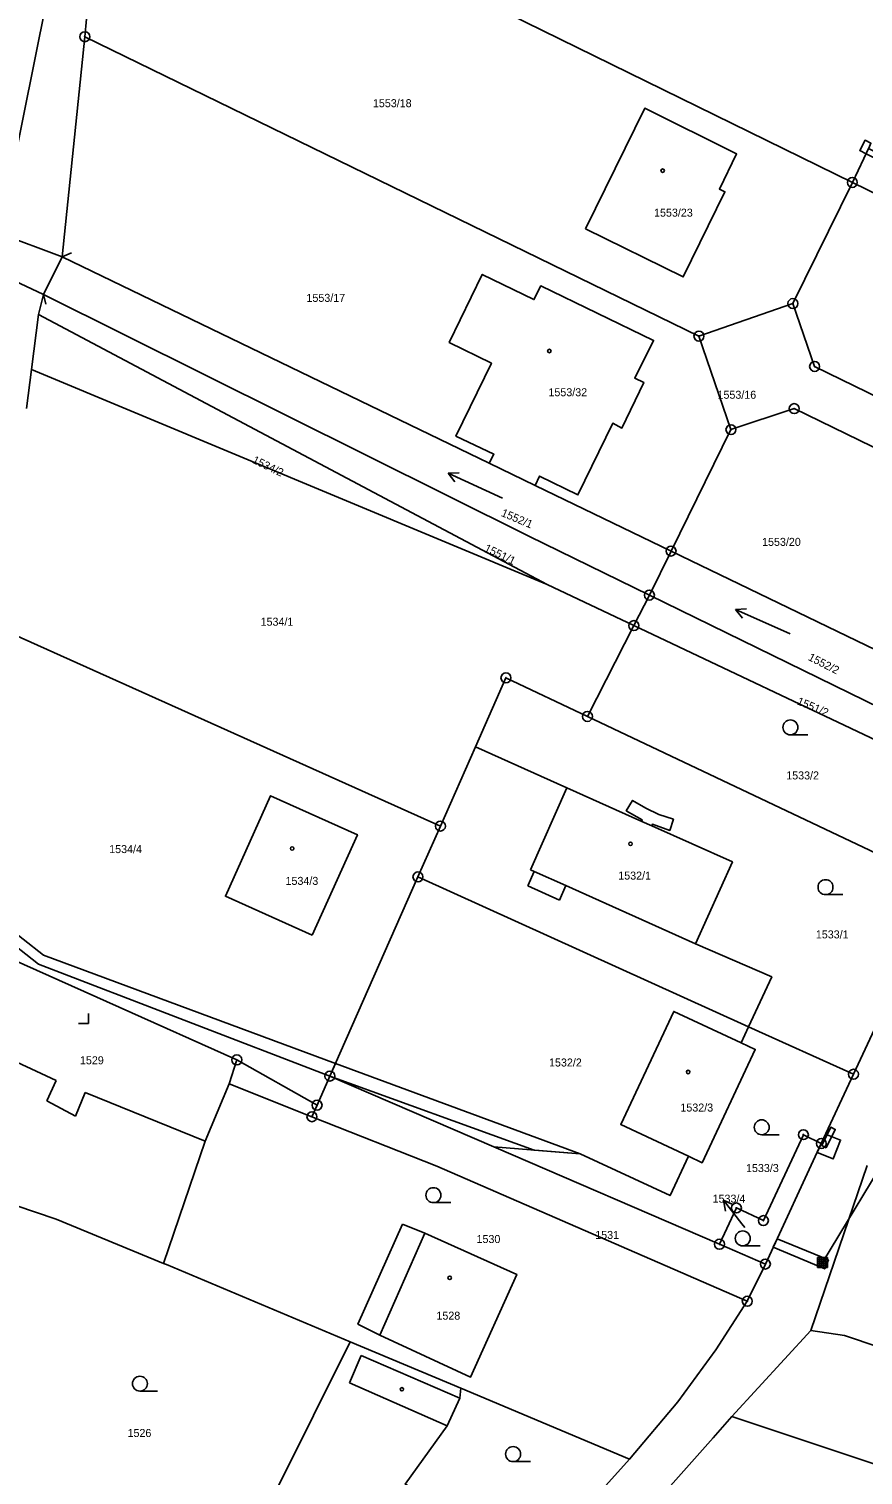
# Model space of a CAD drawing. Extents: x -587171 to -555306, y -1167727 to -1074732.
# Drawn here: x -559814.4 to -559730.7, y -1075878.4 to -1075733.4 of the extents above; entities that cross this region are included whole.
import ezdxf

# ---------------------------------------------------------------- set-up
doc = ezdxf.new("R2010")
doc.units = 0
for name, color, linetype in [('Hranice parcel', 7, 'Continuous'), ('Parcelní čísla', 7, 'Continuous'), ('Pop  PČ popisy', 7, 'Continuous'), ('Poz předměty', 7, 'Continuous'), ('Vnitřní kresba', 7, 'Continuous'), ('Věcná břemena k části', 7, 'Continuous'), ('Značky bodu BP', 7, 'Continuous'), ('Značky budov', 7, 'Continuous'), ('Značky kultur', 7, 'Continuous')]:
    doc.layers.add(name, color=color, linetype=linetype)

msp = doc.modelspace()

# ---------------------------------------------------------------- linework, layer by layer
at = {"layer": 'Hranice parcel'}
for p, q in [((-559731.8, -1075748.76), (-559796.1, -1075717.18)), ((-559811.02, -1075756.21), (-559808.75, -1075734.14)), ((-559747.18, -1075764.18), (-559808.75, -1075734.14)), ((-559730.08, -1075745.15), (-559731.8, -1075748.76)), ((-559737.76, -1075760.91), (-559731.8, -1075748.76)), ((-559692.3, -1075768.16), (-559731.8, -1075748.76)), ((-559812.91, -1075760), (-559811.02, -1075756.21)), ((-559811.02, -1075756.21), (-559768.2, -1075776.93)), ((-559813.39, -1075762.02), (-559812.91, -1075760)), ((-559737.76, -1075760.91), (-559747.18, -1075764.18)), ((-559814.1, -1075767.51), (-559813.39, -1075762.02)), ((-559813.39, -1075762.02), (-559762.4, -1075789.09)), ((-559747.18, -1075764.18), (-559743.97, -1075773.56)), ((-559814.61, -1075771.43), (-559814.1, -1075767.51)), ((-559762.4, -1075789.09), (-559814.1, -1075767.51)), ((-559749.98, -1075785.74), (-559743.97, -1075773.56)), ((-559763.6, -1075779.15), (-559768.2, -1075776.93)), ((-559763.6, -1075779.15), (-559749.98, -1075785.74)), ((-559752.15, -1075790.16), (-559749.98, -1075785.74)), ((-559749.98, -1075785.74), (-559714.26, -1075803.02)), ((-559762.4, -1075789.09), (-559753.71, -1075793.22)), ((-559753.71, -1075793.22), (-559752.15, -1075790.16)), ((-559717.12, -1075807.32), (-559752.15, -1075790.16)), ((-559773.1, -1075813.33), (-559815.81, -1075794.14)), ((-559753.71, -1075793.22), (-559758.36, -1075802.33)), ((-559753.71, -1075793.22), (-559718.54, -1075809.9)), ((-559722.85, -1075819.18), (-559758.36, -1075802.33)), ((-559769.59, -1075805.38), (-559773.1, -1075813.33)), ((-559775.35, -1075818.43), (-559773.1, -1075813.33)), ((-559784.18, -1075838.41), (-559775.35, -1075818.43)), ((-559775.35, -1075818.43), (-559742.2, -1075833.46)), ((-559722.85, -1075819.18), (-559731.69, -1075838.23)), ((-559742.95, -1075835.07), (-559742.2, -1075833.46)), ((-559742.2, -1075833.46), (-559731.69, -1075838.23)), ((-559785.98, -1075842.49), (-559794.29, -1075839.2)), ((-559767.73, -1075845.51), (-559784.18, -1075838.41)), ((-559731.69, -1075838.23), (-559734.91, -1075845.17)), ((-559745.12, -1075855.28), (-559767.73, -1075845.51)), ((-559734.91, -1075845.17), (-559740.52, -1075857.27)), ((-559735.95, -1075863.92), (-559730.31, -1075847.37)), ((-559740.52, -1075857.27), (-559745.12, -1075855.28)), ((-559740.52, -1075857.27), (-559742.33, -1075861)), ((-559743.87, -1075872.57), (-559735.95, -1075863.92)), ((-559771.04, -1075869.73), (-559782.14, -1075865.06)), ((-559771.04, -1075869.73), (-559754.13, -1075876.85))]:
    msp.add_line(p, q, dxfattribs=at)
for points in [[(-559808.75, -1075734.14), (-559808.57, -1075732.35), (-559796.1, -1075717.18)], [(-559812.62, -1075730.76), (-559817.32, -1075753.87), (-559818.88, -1075757.17), (-559822.15, -1075761.67)], [(-559758.56, -1075753.42), (-559752.61, -1075741.32), (-559743.41, -1075745.89), (-559745.12, -1075749.43), (-559744.58, -1075749.7), (-559748.75, -1075758.23), (-559758.56, -1075753.42)], [(-559768.2, -1075776.93), (-559767.73, -1075776.03), (-559771.54, -1075774.2), (-559767.99, -1075766.9), (-559772.22, -1075764.81), (-559768.9, -1075757.99), (-559763.72, -1075760.51), (-559763.04, -1075759.14), (-559751.73, -1075764.6), (-559753.61, -1075768.39), (-559752.72, -1075768.82), (-559754.91, -1075773.41), (-559755.83, -1075772.92), (-559759.31, -1075780.1), (-559763.15, -1075778.22), (-559763.6, -1075779.15)], [(-559752.15, -1075790.16), (-559764.23, -1075784.25), (-559812.91, -1075760)], [(-559700.23, -1075780.74), (-559705.08, -1075782.11), (-559735.58, -1075767.22), (-559737.76, -1075760.91)], [(-559743.97, -1075773.56), (-559737.63, -1075771.45), (-559707.59, -1075786.09), (-559706.7, -1075791.01)], [(-559758.36, -1075802.33), (-559766.53, -1075798.46), (-559769.59, -1075805.38)], [(-559769.59, -1075805.38), (-559760.42, -1075809.49), (-559752.91, -1075812.86), (-559752.88, -1075812.71), (-559754.47, -1075811.8), (-559753.84, -1075810.76), (-559752.51, -1075811.55), (-559751.19, -1075812.16), (-559749.74, -1075812.64), (-559750.1, -1075813.77), (-559751.85, -1075813.14), (-559751.91, -1075813.31), (-559743.83, -1075816.93), (-559747.51, -1075825.13), (-559739.88, -1075828.47), (-559742.2, -1075833.46)], [(-559785.96, -1075824.28), (-559781.43, -1075814.2), (-559790.13, -1075810.29), (-559794.65, -1075820.37), (-559785.96, -1075824.28)], [(-559794.29, -1075839.2), (-559793.51, -1075836.79), (-559817.1, -1075826.2)], [(-559748.24, -1075846.45), (-559755.02, -1075843.27), (-559749.7, -1075831.92), (-559742.95, -1075835.07)], [(-559742.95, -1075835.07), (-559741.54, -1075835.73), (-559746.86, -1075847.1), (-559748.24, -1075846.45)], [(-559800.85, -1075857.2), (-559796.69, -1075844.93), (-559794.29, -1075839.2)], [(-559784.18, -1075838.41), (-559785.47, -1075841.33), (-559785.98, -1075842.49)], [(-559742.33, -1075861), (-559773.46, -1075847.44), (-559785.98, -1075842.49)], [(-559745.12, -1075855.28), (-559743.43, -1075851.64), (-559740.72, -1075852.91), (-559736.71, -1075844.29), (-559734.91, -1075845.17)], [(-559767.73, -1075845.51), (-559759.1, -1075846.22), (-559750.07, -1075850.4), (-559748.24, -1075846.45)], [(-559821, -1075850.76), (-559817.67, -1075850.72), (-559811.62, -1075852.78), (-559800.85, -1075857.2)], [(-559776.9, -1075853.26), (-559781.38, -1075863.29), (-559779.17, -1075864.41), (-559770.08, -1075868.61), (-559765.45, -1075858.31), (-559774.66, -1075854.18), (-559776.9, -1075853.26)], [(-559800.85, -1075857.2), (-559800.57, -1075857.31), (-559782.14, -1075865.06)], [(-559742.33, -1075861), (-559745.48, -1075865.87), (-559749.31, -1075871.1), (-559754.13, -1075876.85)], [(-559735.95, -1075863.92), (-559732.58, -1075864.43), (-559707.97, -1075872.72), (-559694.43, -1075877.61)], [(-559782.14, -1075865.06), (-559793.14, -1075887.17), (-559787.95, -1075890.13), (-559783.64, -1075892.41), (-559785.07, -1075895.16), (-559777.29, -1075899.22)], [(-559777.29, -1075899.22), (-559774.71, -1075894.36), (-559773.08, -1075895.27), (-559772.14, -1075894.77), (-559771.44, -1075893.27), (-559771.43, -1075892.12), (-559773.03, -1075891.2), (-559770.46, -1075886.37), (-559773.26, -1075884.9), (-559771.75, -1075881.96), (-559776.65, -1075879.35), (-559772.43, -1075873.5), (-559771.15, -1075870.71), (-559771.04, -1075869.73)], [(-559759.39, -1075890.96), (-559756.96, -1075887.31), (-559745.77, -1075874.71), (-559743.87, -1075872.57)], [(-559718.92, -1075880.89), (-559742.59, -1075873), (-559743.87, -1075872.57)], [(-559754.13, -1075876.85), (-559760.1, -1075883.46), (-559765.88, -1075889.07), (-559774.97, -1075900.54), (-559781.59, -1075907.31)]]:
    msp.add_lwpolyline(points, dxfattribs=at)
at = {"layer": 'Pop  PČ popisy'}
for p, q in [((-559742.88, -1075853.22), (-559744.73, -1075850.85)), ((-559744.73, -1075850.85), (-559743.72, -1075851.34)), ((-559744.73, -1075850.85), (-559744.51, -1075851.95)), ((-559742.59, -1075853.59), (-559742.88, -1075853.22))]:
    msp.add_line(p, q, dxfattribs=at)
at = {"layer": 'Poz předměty'}
for p, q in [((-559713.43, -1075821.67), (-559734.8, -1075857.12)), ((-559735.3, -1075856.62), (-559734.3, -1075856.62)), ((-559735.3, -1075857.62), (-559735.3, -1075856.62)), ((-559735.1, -1075857.62), (-559735.1, -1075856.62)), ((-559734.9, -1075857.62), (-559734.9, -1075856.62)), ((-559734.7, -1075857.62), (-559734.7, -1075856.62)), ((-559734.5, -1075857.62), (-559734.5, -1075856.62)), ((-559734.3, -1075857.62), (-559734.3, -1075856.62)), ((-559735.3, -1075856.82), (-559734.3, -1075856.82)), ((-559735.3, -1075857.02), (-559734.3, -1075857.02)), ((-559735.3, -1075857.22), (-559734.3, -1075857.22)), ((-559735.3, -1075857.42), (-559734.3, -1075857.42)), ((-559735.3, -1075857.62), (-559734.3, -1075857.62))]:
    msp.add_line(p, q, dxfattribs=at)
at = {"layer": 'Vnitřní kresba'}
for p, q in [((-559817.32, -1075753.87), (-559811.02, -1075756.21)), ((-559810.1, -1075755.82), (-559811.02, -1075756.21)), ((-559818.88, -1075757.17), (-559812.91, -1075760)), ((-559812.67, -1075760.97), (-559812.91, -1075760)), ((-559760.42, -1075809.49), (-559764.08, -1075817.71)), ((-559751.91, -1075813.31), (-559752.91, -1075812.86)), ((-559764.34, -1075819.33), (-559763.7, -1075817.88)), ((-559764.08, -1075817.71), (-559763.7, -1075817.88)), ((-559763.7, -1075817.88), (-559760.52, -1075819.3)), ((-559761.17, -1075820.77), (-559764.34, -1075819.33)), ((-559760.52, -1075819.3), (-559761.17, -1075820.77)), ((-559760.52, -1075819.3), (-559747.51, -1075825.13)), ((-559821.3, -1075834.37), (-559811.62, -1075838.87)), ((-559793.51, -1075836.79), (-559785.47, -1075841.33)), ((-559811.62, -1075838.87), (-559812.56, -1075840.9)), ((-559809.69, -1075842.45), (-559808.71, -1075840.05)), ((-559808.71, -1075840.05), (-559796.69, -1075844.93)), ((-559812.56, -1075840.9), (-559809.69, -1075842.45)), ((-559774.66, -1075854.18), (-559779.17, -1075864.41)), ((-559781.04, -1075866.45), (-559782.22, -1075869.19)), ((-559771.15, -1075870.71), (-559781.04, -1075866.45)), ((-559782.22, -1075869.19), (-559772.43, -1075873.5))]:
    msp.add_line(p, q, dxfattribs=at)
at = {"layer": 'Věcná břemena k části'}
for points in [[(-559730.43, -1075745.88), (-559690.65, -1075765.53), (-559690.3, -1075764.99), (-559730.17, -1075745.34), (-559730.08, -1075745.15), (-559729.93, -1075744.83), (-559730.53, -1075744.53), (-559731.05, -1075745.57)], [(-559816.98, -1075823.08), (-559817.03, -1075824.32), (-559813.39, -1075827.17), (-559784.18, -1075838.41), (-559783.62, -1075837.14), (-559812.89, -1075826.29)], [(-559783.62, -1075837.14), (-559784.18, -1075838.41), (-559763.7, -1075845.84), (-559759.1, -1075846.22)], [(-559734.42, -1075845.6), (-559733.52, -1075843.76), (-559733.97, -1075843.54), (-559734.87, -1075845.38)], [(-559734.48, -1075844.24), (-559735.33, -1075846.09), (-559733.73, -1075846.72), (-559732.98, -1075844.83)], [(-559734.18, -1075856.84), (-559739.35, -1075854.74), (-559739.73, -1075855.58), (-559734.57, -1075857.76)]]:
    msp.add_lwpolyline(points, close=True, dxfattribs=at)
at = {"layer": 'Značky bodu BP'}
for centre, radius in [((-559808.75, -1075734.14), 0.5), ((-559808.75, -1075734.14), 0.0303), ((-559731.8, -1075748.76), 0.5), ((-559731.8, -1075748.76), 0.0303), ((-559737.76, -1075760.91), 0.5), ((-559737.76, -1075760.91), 0.0303), ((-559747.18, -1075764.18), 0.5), ((-559747.18, -1075764.18), 0.0303), ((-559735.58, -1075767.22), 0.5), ((-559735.58, -1075767.22), 0.0303), ((-559737.63, -1075771.45), 0.5), ((-559737.63, -1075771.45), 0.0303), ((-559743.97, -1075773.56), 0.5), ((-559743.97, -1075773.56), 0.0303), ((-559749.98, -1075785.74), 0.5), ((-559749.98, -1075785.74), 0.0303), ((-559752.15, -1075790.16), 0.5), ((-559752.15, -1075790.16), 0.0303), ((-559753.71, -1075793.22), 0.5), ((-559753.71, -1075793.22), 0.0303), ((-559766.53, -1075798.46), 0.5), ((-559766.53, -1075798.46), 0.0303), ((-559758.36, -1075802.33), 0.5), ((-559758.36, -1075802.33), 0.0303), ((-559773.1, -1075813.33), 0.5), ((-559773.1, -1075813.33), 0.0303), ((-559775.35, -1075818.43), 0.5), ((-559775.35, -1075818.43), 0.0303), ((-559793.51, -1075836.79), 0.5), ((-559793.51, -1075836.79), 0.0303), ((-559731.69, -1075838.23), 0.5), ((-559784.18, -1075838.41), 0.5), ((-559784.18, -1075838.41), 0.0303), ((-559731.69, -1075838.23), 0.0303), ((-559785.98, -1075842.49), 0.5), ((-559785.47, -1075841.33), 0.5), ((-559785.47, -1075841.33), 0.0303), ((-559785.98, -1075842.49), 0.0303), ((-559736.71, -1075844.29), 0.5), ((-559736.71, -1075844.29), 0.0303), ((-559734.91, -1075845.17), 0.5), ((-559734.91, -1075845.17), 0.0303), ((-559743.43, -1075851.64), 0.5), ((-559743.43, -1075851.64), 0.0303), ((-559740.72, -1075852.91), 0.5), ((-559740.72, -1075852.91), 0.0303), ((-559745.12, -1075855.28), 0.5), ((-559745.12, -1075855.28), 0.0303), ((-559740.52, -1075857.27), 0.5), ((-559740.52, -1075857.27), 0.0303), ((-559742.33, -1075861), 0.5), ((-559742.33, -1075861), 0.0303)]:
    msp.add_circle(centre, radius, dxfattribs=at)
at = {"layer": 'Značky budov'}
for centre in [(-559750.82, -1075747.57), (-559762.18, -1075765.67), (-559787.97, -1075815.58), (-559754.04, -1075815.11), (-559748.26, -1075838), (-559772.17, -1075858.65), (-559776.96, -1075869.83)]:
    msp.add_circle(centre, 0.175, dxfattribs=at)
at = {"layer": 'Značky kultur'}
for p, q in [((-559772.33, -1075777.92), (-559771.23, -1075777.88)), ((-559766.89, -1075780.45), (-559772.33, -1075777.92)), ((-559772.33, -1075777.92), (-559771.66, -1075778.78)), ((-559743.5, -1075791.61), (-559742.41, -1075791.55)), ((-559738.02, -1075794.05), (-559743.5, -1075791.61)), ((-559743.5, -1075791.61), (-559742.81, -1075792.47)), ((-559738.01, -1075804.18), (-559736.26, -1075804.18)), ((-559734.49, -1075820.21), (-559732.74, -1075820.21)), ((-559809.39, -1075833.13), (-559808.39, -1075833.13)), ((-559808.39, -1075833.13), (-559808.39, -1075832.13)), ((-559740.89, -1075844.3), (-559739.14, -1075844.3)), ((-559773.8, -1075851.11), (-559772.05, -1075851.11)), ((-559742.79, -1075855.45), (-559741.04, -1075855.45)), ((-559803.23, -1075870.02), (-559801.48, -1075870.02)), ((-559765.81, -1075877.09), (-559764.06, -1075877.09))]:
    msp.add_line(p, q, dxfattribs=at)
for centre in [(-559738.01, -1075803.43), (-559734.49, -1075819.46), (-559740.89, -1075843.55), (-559773.8, -1075850.36), (-559742.79, -1075854.7), (-559803.23, -1075869.27), (-559765.81, -1075876.34)]:
    msp.add_circle(centre, 0.75, dxfattribs=at)

# ---------------------------------------------------------------- texts
at = {"layer": 'Parcelní čísla'}
for s, p in [('1553/18', (-559779.87, -1075741.21)), ('1553/23', (-559751.68, -1075752.19)), ('1553/17', (-559786.53, -1075760.74)), ('1553/32', (-559762.27, -1075770.21)), ('1553/16', (-559745.32, -1075770.46)), ('1553/20', (-559740.85, -1075785.22)), ('1534/1', (-559791.13, -1075793.23)), ('1533/2', (-559738.43, -1075808.65)), ('1534/4', (-559806.31, -1075816.04)), ('1534/3', (-559788.63, -1075819.23)), ('1532/1', (-559755.27, -1075818.7)), ('1533/1', (-559735.46, -1075824.6)), ('1529', (-559809.24, -1075837.23)), ('1532/2', (-559762.21, -1075837.45)), ('1532/3', (-559749.04, -1075841.97)), ('1533/3', (-559742.46, -1075848.04)), ('1533/4', (-559745.81, -1075851.11)), ('1530', (-559769.48, -1075855.16)), ('1531', (-559757.58, -1075854.75)), ('1528', (-559773.5, -1075862.85)), ('1526', (-559804.47, -1075874.62))]:
    msp.add_text(s, height=0.803, dxfattribs=at).set_placement(p)
for s, rotation, p in [('1534/2', 334, (-559792.03, -1075776.86)), ('1552/1', 337, (-559767.08, -1075782.2)), ('1551/1', 334, (-559768.77, -1075785.71)), ('1552/2', 333, (-559736.3, -1075796.64)), ('1551/2', 337, (-559737.42, -1075801.09))]:
    msp.add_text(s, height=0.803, rotation=rotation, dxfattribs=at).set_placement(p)

doc.saveas('drawing.dxf')
